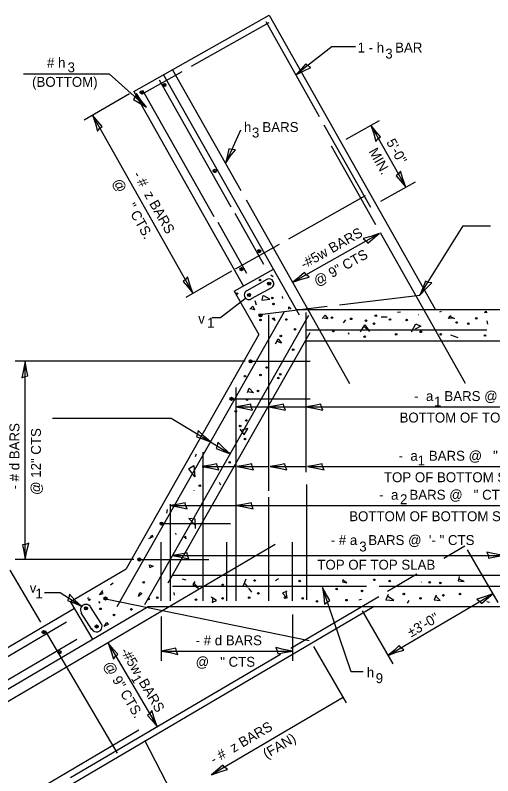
# Model space of a CAD drawing. Extents: x 2133490 to 2172050, y 2138301 to 2145980.
# Drawn here: x 2138402.7 to 2138691.7, y 2144827.1 to 2145287.5 of the extents above; entities that cross this region are included whole.
import ezdxf

# ---------------------------------------------------------------- set-up
doc = ezdxf.new("R2010")
doc.units = 0
for name, color, linetype in [('Level 40', 7, 'Continuous'), ('Level 63', 7, 'Continuous'), ('ROW_PR_Notes', 7, 'Continuous')]:
    doc.layers.add(name, color=color, linetype=linetype)

msp = doc.modelspace()

# ---------------------------------------------------------------- linework, layer by layer
at = {"layer": 'Level 40'}
msp.add_line((2138581.04, 2145095.24), (2138495.13, 2144943.62), dxfattribs=at)
for centre, radius in [((2138492.97, 2145245.3), 0.945), ((2138479.23, 2145240.84), 0.945), ((2138493.24, 2145245.3), 0.473), ((2138479.31, 2145240.65), 0.473), ((2138523.42, 2145193.34), 0.945), ((2138523.44, 2145193.28), 0.945), ((2138523.69, 2145192.86), 0.473), ((2138550.26, 2145144.7), 0.945), ((2138550.09, 2145144.79), 0.473), ((2138539.6, 2145133.83), 0.945), ((2138539.69, 2145133.64), 0.473), ((2138550.75, 2145127.23), 0.473), ((2138556.35, 2145125.03), 0.945), ((2138556.35, 2145125.03), 0.473), ((2138536.94, 2145119.02), 0.473), ((2138544.15, 2145118.22), 0.945), ((2138544.15, 2145118.22), 0.945), ((2138544.15, 2145118.22), 0.473), ((2138558.21, 2145116.41), 0.473), ((2138558.95, 2145112.68), 0.473), ((2138551.12, 2145105.86), 0.945), ((2138551.12, 2145105.86), 0.473), ((2138551.12, 2145102.98), 0.473), ((2138566.79, 2145103.35), 0.473), ((2138594.4, 2145104.47), 0.473), ((2138605.96, 2145103.73), 0.473), ((2138620.89, 2145105.59), 0.473), ((2138629.47, 2145103.35), 0.473), ((2138639.54, 2145102.98), 0.473), ((2138681.7, 2145104.1), 0.473), ((2138614.92, 2145102.61), 0.473), ((2138619.77, 2145100.74), 0.473), ((2138669.76, 2145101.49), 0.473), ((2138676.85, 2145100.74), 0.473), ((2138572.01, 2145097.38), 0.473), ((2138595.14, 2145096.26), 0.473), ((2138633.2, 2145094.4), 0.473), ((2138648.12, 2145095.89), 0.473), ((2138660.06, 2145094.4), 0.473), ((2138686.92, 2145093.65), 0.473), ((2138563.43, 2145093.28), 0.473), ((2138614.17, 2145092.91), 0.473), ((2138570.89, 2145085.07), 0.473), ((2138545.11, 2145078.02), 0.945), ((2138545.11, 2145078.02), 0.473), ((2138554.85, 2145074.25), 0.473), ((2138541.79, 2145069.03), 0.473), ((2138551.12, 2145069.77), 0.473), ((2138561.94, 2145067.91), 0.473), ((2138563.06, 2145070.15), 0.473), ((2138549.63, 2145060.07), 0.473), ((2138533.55, 2145055.34), 0.945), ((2138533.55, 2145055.34), 0.473), ((2138542.91, 2145054.85), 0.473), ((2138536.2, 2145047.76), 0.473), ((2138538.81, 2145038.81), 0.473), ((2138542.54, 2145042.17), 0.473), ((2138541.79, 2145030.97), 0.473), ((2138532.47, 2145016.8), 0.473), ((2138514.37, 2145002.8), 0.473), ((2138491.28, 2144979.74), 0.945), ((2138491.28, 2144979.74), 0.473), ((2138477.82, 2144958.01), 0.945), ((2138477.82, 2144958.01), 0.473), ((2138480.42, 2144944.23), 0.473), ((2138528.18, 2144942.74), 0.473), ((2138547.58, 2144945.35), 0.473), ((2138574.81, 2144944.97), 0.473), ((2138619.96, 2144945.72), 0.473), ((2138629.28, 2144944.97), 0.473), ((2138653.53, 2144944.23), 0.473), ((2138659.88, 2144943.86), 0.473), ((2138549.81, 2144937.51), 0.473), ((2138597.2, 2144940.13), 0.473), ((2138612.49, 2144939.01), 0.473), ((2138637.86, 2144937.14), 0.473), ((2138671.82, 2144937.14), 0.473), ((2138447.59, 2144933.78), 0.473), ((2138457.29, 2144934.44), 0.945), ((2138457.13, 2144934.29), 0.473), ((2138483.4, 2144934.16), 0.473), ((2138488.63, 2144934.9), 0.473), ((2138512.13, 2144933.78), 0.473), ((2138528.18, 2144934.53), 0.473), ((2138544.22, 2144934.9), 0.473), ((2138565.86, 2144934.9), 0.473), ((2138576.68, 2144934.53), 0.473), ((2138585.26, 2144932.66), 0.473), ((2138603.17, 2144933.41), 0.473), ((2138647.94, 2144934.53), 0.473), ((2138661.74, 2144936.39), 0.473), ((2138445.46, 2144928.53), 0.945), ((2138445.46, 2144928.53), 0.473), ((2138454.3, 2144928.19), 0.473), ((2138472.96, 2144927.81), 0.473), ((2138462.51, 2144924.46), 0.473), ((2138419.85, 2144914.03), 0.945), ((2138420.09, 2144914.03), 0.473), ((2138451.93, 2144917.48), 0.945), ((2138451.93, 2144917.48), 0.473), ((2138429.51, 2144901.95), 0.945), ((2138429.51, 2144901.46), 0.473)]:
    msp.add_circle(centre, radius, dxfattribs=at)
at = {"layer": 'Level 63'}
for p, q in [((2138594.52, 2145268.54), (2138608.64, 2145268.54)), ((2138471.92, 2145239.84), (2138444.31, 2145223.97)), ((2138449.38, 2145227.05), (2138510.11, 2145119.36)), ((2138603.03, 2145212.58), (2138623.1, 2145223.76)), ((2138617.83, 2145220.87), (2138638.96, 2145183.39)), ((2138623.95, 2145175.03), (2138644.99, 2145186.75)), ((2138647.61, 2145118.13), (2138673.81, 2145159.93)), ((2138673.81, 2145159.93), (2138690.2, 2145159.93)), ((2138570.76, 2145125.95), (2138623, 2145155.41)), ((2138533.57, 2145132.57), (2138505.95, 2145116.7)), ((2138541.81, 2145078.02), (2138402.72, 2145078.02)), ((2138408.72, 2144958.01), (2138408.72, 2145078.02)), ((2138536.31, 2145050.47), (2138556.16, 2145050.47)), ((2138556.16, 2145050.47), (2138578.77, 2145050.47)), ((2138578.77, 2145050.47), (2138787.43, 2145050.47)), ((2138515.84, 2145014.34), (2138536.18, 2145014.34)), ((2138536.93, 2145014.34), (2138556.22, 2145014.34)), ((2138556.97, 2145014.34), (2138578.5, 2145014.34)), ((2138579.53, 2145014.34), (2138767.82, 2145014.34)), ((2138496.67, 2144990.73), (2138535.86, 2144990.73)), ((2138536.7, 2144990.73), (2138749.98, 2144990.73)), ((2138497.8, 2144960.46), (2138697.99, 2144960.46)), ((2138676.17, 2144963.84), (2138694.65, 2144932.06)), ((2138474.51, 2144958.01), (2138402.72, 2144958.01)), ((2138418.12, 2144920.08), (2138399.59, 2144951.55)), ((2138628.24, 2144899.98), (2138691.65, 2144937.26)), ((2138570.45, 2144924.75), (2138570.45, 2144896.62)), ((2138612.58, 2144926.87), (2138631.23, 2144894.79)), ((2138491.07, 2144923.44), (2138491.07, 2144896.62)), ((2138458.88, 2144907.46), (2138488.61, 2144856.87)), ((2138491.07, 2144902.62), (2138570.45, 2144902.62)), ((2138481.01, 2144848.59), (2138497, 2144817.45))]:
    msp.add_line(p, q, dxfattribs=at)
for points in [[(2138581.66, 2145255.87), (2138579.83, 2145256.89), (2138578.45, 2145258.15), (2138575.9, 2145255.13), (2138572.49, 2145251.38), (2138577.29, 2145253.89)], [(2138475.99, 2145240.04), (2138475.31, 2145238.07), (2138474.31, 2145236.49), (2138477.73, 2145234.5), (2138482.03, 2145231.8), (2138478.71, 2145236.09)], [(2138452.47, 2145217.31), (2138453.75, 2145218.96), (2138455.2, 2145220.14), (2138452.6, 2145223.12), (2138449.38, 2145227.05), (2138451.16, 2145221.92)], [(2138620.92, 2145211.13), (2138622.19, 2145212.78), (2138623.64, 2145213.96), (2138621.04, 2145216.94), (2138617.83, 2145220.87), (2138619.6, 2145215.74)], [(2138535.91, 2145206.1), (2138533.82, 2145206.15), (2138532.01, 2145206.63), (2138531.15, 2145202.77), (2138529.87, 2145197.86), (2138532.96, 2145202.32)], [(2138635.87, 2145193.13), (2138634.6, 2145191.48), (2138633.14, 2145190.3), (2138635.75, 2145187.32), (2138638.96, 2145183.39), (2138637.18, 2145188.52)], [(2138613.26, 2145152.32), (2138614.91, 2145151.04), (2138616.09, 2145149.59), (2138619.07, 2145152.2), (2138623, 2145155.41), (2138617.88, 2145153.63)], [(2138580.5, 2145129.04), (2138578.85, 2145130.31), (2138577.67, 2145131.77), (2138574.69, 2145129.16), (2138570.76, 2145125.95), (2138575.89, 2145127.73)], [(2138507.02, 2145129.1), (2138505.74, 2145127.45), (2138504.29, 2145126.27), (2138506.9, 2145123.29), (2138510.11, 2145119.36), (2138508.33, 2145124.48)], [(2138654.69, 2145125.49), (2138652.63, 2145125.82), (2138650.9, 2145126.54), (2138649.53, 2145122.83), (2138647.61, 2145118.13), (2138651.26, 2145122.14)], [(2138406.63, 2145068.02), (2138408.55, 2145068.84), (2138410.4, 2145069.15), (2138409.59, 2145073.02), (2138408.72, 2145078.02), (2138407.75, 2145072.69)], [(2138546.31, 2145048.37), (2138545.5, 2145050.3), (2138545.18, 2145052.14), (2138541.31, 2145051.33), (2138536.31, 2145050.47), (2138541.65, 2145049.5)], [(2138566.15, 2145048.37), (2138565.34, 2145050.3), (2138565.03, 2145052.14), (2138561.16, 2145051.33), (2138556.16, 2145050.47), (2138561.49, 2145049.5)], [(2138588.77, 2145048.37), (2138587.96, 2145050.3), (2138587.64, 2145052.14), (2138583.77, 2145051.33), (2138578.77, 2145050.47), (2138584.11, 2145049.5)], [(2138513.35, 2145036.18), (2138513.05, 2145034.11), (2138512.36, 2145032.37), (2138516.09, 2145031.06), (2138520.82, 2145029.2), (2138516.76, 2145032.8)], [(2138525.22, 2145028.99), (2138524.92, 2145026.92), (2138524.23, 2145025.18), (2138527.96, 2145023.87), (2138532.68, 2145022.02), (2138528.62, 2145025.61)], [(2138525.84, 2145012.25), (2138525.02, 2145014.17), (2138524.71, 2145016.01), (2138520.84, 2145015.2), (2138515.84, 2145014.34), (2138521.17, 2145013.37)], [(2138546.93, 2145012.25), (2138546.11, 2145014.17), (2138545.8, 2145016.01), (2138541.93, 2145015.2), (2138536.93, 2145014.34), (2138542.26, 2145013.37)], [(2138566.97, 2145012.25), (2138566.15, 2145014.17), (2138565.84, 2145016.01), (2138561.97, 2145015.2), (2138556.97, 2145014.34), (2138562.3, 2145013.37)], [(2138589.53, 2145012.25), (2138588.71, 2145014.17), (2138588.4, 2145016.01), (2138584.53, 2145015.2), (2138579.53, 2145014.34), (2138584.86, 2145013.37)], [(2138506.66, 2144988.64), (2138505.85, 2144990.56), (2138505.54, 2144992.4), (2138501.67, 2144991.59), (2138496.67, 2144990.73), (2138502, 2144989.76)], [(2138546.7, 2144988.64), (2138545.88, 2144990.56), (2138545.57, 2144992.4), (2138541.7, 2144991.59), (2138536.7, 2144990.73), (2138542.03, 2144989.76)], [(2138410.82, 2144968), (2138408.89, 2144967.19), (2138407.05, 2144966.88), (2138407.86, 2144963.01), (2138408.72, 2144958.01), (2138409.69, 2144963.34)], [(2138507.8, 2144958.37), (2138506.99, 2144960.29), (2138506.67, 2144962.13), (2138502.8, 2144961.33), (2138497.8, 2144960.46), (2138503.14, 2144959.49)], [(2138687.99, 2144962.55), (2138688.8, 2144960.63), (2138689.12, 2144958.79), (2138692.99, 2144959.59), (2138697.99, 2144960.46), (2138692.65, 2144961.43)], [(2138589.89, 2144930.91), (2138591.45, 2144932.3), (2138593.09, 2144933.19), (2138591.08, 2144936.6), (2138588.65, 2144941.05), (2138589.45, 2144935.69)], [(2138435.5, 2144936.98), (2138435.14, 2144934.92), (2138434.4, 2144933.21), (2138438.09, 2144931.78), (2138442.76, 2144929.8), (2138438.8, 2144933.51)], [(2138681.97, 2144934), (2138683.65, 2144932.75), (2138684.85, 2144931.32), (2138687.78, 2144933.98), (2138691.65, 2144937.26), (2138686.56, 2144935.39)], [(2138462.14, 2144897.78), (2138463.38, 2144899.46), (2138464.81, 2144900.66), (2138462.16, 2144903.59), (2138458.88, 2144907.46), (2138460.74, 2144902.37)], [(2138637.92, 2144903.25), (2138636.24, 2144904.49), (2138635.04, 2144905.92), (2138632.11, 2144903.26), (2138628.24, 2144899.98), (2138633.33, 2144901.85)], [(2138501.07, 2144900.53), (2138500.25, 2144902.45), (2138499.94, 2144904.3), (2138496.07, 2144903.49), (2138491.07, 2144902.62), (2138496.4, 2144901.65)], [(2138560.45, 2144904.72), (2138561.27, 2144902.79), (2138561.58, 2144900.95), (2138565.45, 2144901.76), (2138570.45, 2144902.62), (2138565.12, 2144903.59)], [(2138485.35, 2144866.55), (2138484.1, 2144864.88), (2138482.67, 2144863.67), (2138485.33, 2144860.74), (2138488.61, 2144856.87), (2138486.74, 2144861.96)], [(2138531.16, 2144830.89), (2138529.49, 2144832.13), (2138528.28, 2144833.56), (2138525.35, 2144830.91), (2138521.48, 2144827.63), (2138526.57, 2144829.49)]]:
    msp.add_lwpolyline(points, close=True, dxfattribs=at)
at = {"layer": 'ROW_PR_Notes'}
for p, q in [((2138474.38, 2145241.25), (2138556.44, 2145287.53)), ((2138556.44, 2145287.53), (2138656.73, 2145109.67)), ((2138509.34, 2145256.63), (2138556.41, 2145283.17)), ((2138554.23, 2145283.74), (2138586.69, 2145226.18)), ((2138479.33, 2145239.71), (2138503.79, 2145253.5)), ((2138492.49, 2145251.46), (2138574.47, 2145106.09)), ((2138497.92, 2145254.52), (2138539.11, 2145181.47)), ((2138489.82, 2145248.44), (2138533.13, 2145171.62)), ((2138474.38, 2145241.25), (2138540.76, 2145123.54)), ((2138479.65, 2145242.18), (2138522.78, 2145165.68)), ((2138589.49, 2145221.22), (2138617.67, 2145171.25)), ((2138593.85, 2145208.52), (2138620.76, 2145160.8)), ((2138568.25, 2145152.15), (2138614.72, 2145178.35)), ((2138542.36, 2145175.71), (2138605.03, 2145064.58)), ((2138535.57, 2145167.63), (2138552.94, 2145136.82)), ((2138525.23, 2145162.24), (2138542.6, 2145131.43)), ((2138623.42, 2145156.09), (2138674.94, 2145064.72)), ((2138536.03, 2145133.98), (2138562.7, 2145149.02)), ((2138535.26, 2145120.44), (2138558.88, 2145133.76)), ((2138554.96, 2145127.51), (2138542.76, 2145120.69)), ((2138557.27, 2145130.4), (2138558.77, 2145129.28)), ((2138557.73, 2145122.56), (2138545.53, 2145115.75)), ((2138535.26, 2145120.44), (2138550.05, 2145094.22)), ((2138552.53, 2145117.92), (2138551.85, 2145114.99)), ((2138556.81, 2145115.67), (2138553.2, 2145117.7)), ((2138564.25, 2145117.25), (2138564.48, 2145116.12)), ((2138598.83, 2145112.21), (2138647.61, 2145118.13)), ((2138526.86, 2145104.5), (2138542.06, 2145116.23)), ((2138548.7, 2145112.06), (2138547.79, 2145114.54)), ((2138551.85, 2145114.99), (2138556.81, 2145115.67)), ((2138565.42, 2145107.92), (2138464.24, 2144929.36)), ((2138544.59, 2145109.51), (2138546.45, 2145111.37)), ((2138547.57, 2145109.13), (2138544.96, 2145109.88)), ((2138546.45, 2145111.37), (2138547.57, 2145109.13)), ((2138550.8, 2145106.38), (2138591.4, 2145111.31)), ((2138568.25, 2145109.54), (2138568.25, 2145111.08)), ((2138568.25, 2145111.08), (2138569.45, 2145110.05)), ((2138569.45, 2145110.05), (2138568.77, 2145109.71)), ((2138813.89, 2145109.21), (2138572.71, 2145109.21)), ((2138634.01, 2145107.83), (2138635.89, 2145108)), ((2138659.52, 2145108), (2138660.72, 2145108.34)), ((2138686.57, 2145107.65), (2138687.6, 2145108.34)), ((2138687.94, 2145107.31), (2138686.92, 2145108)), ((2138687.6, 2145108.34), (2138687.94, 2145107.31)), ((2138580.17, 2145105.81), (2138480.91, 2144930.66)), ((2138521.86, 2145104.5), (2138526.86, 2145104.5)), ((2138556.16, 2144999.6), (2138556.16, 2145106.21)), ((2138559.86, 2145102.69), (2138558.15, 2145103.89)), ((2138558.84, 2145103.72), (2138559.18, 2145104.57)), ((2138559.18, 2145104.57), (2138559.86, 2145102.69)), ((2138578.77, 2145011.01), (2138578.77, 2145107.59)), ((2138588.37, 2145103.95), (2138590.18, 2145105.98)), ((2138591.76, 2145103.72), (2138589.5, 2145104.17)), ((2138590.18, 2145105.98), (2138591.76, 2145103.72)), ((2138601.3, 2145101.3), (2138602.79, 2145103.17)), ((2138624.06, 2145105.03), (2138627.79, 2145105.03)), ((2138646.63, 2145106.34), (2138647, 2145106.34)), ((2138666.15, 2145105.75), (2138664.8, 2145103.95)), ((2138664.8, 2145103.95), (2138665.7, 2145105.3)), ((2138668.41, 2145103.95), (2138665.48, 2145104.17)), ((2138665.7, 2145105.3), (2138668.41, 2145103.95)), ((2138611.59, 2145095.83), (2138614.3, 2145100.11)), ((2138617, 2145096.06), (2138613.4, 2145099.44)), ((2138614.3, 2145100.11), (2138617, 2145096.06)), ((2138636.93, 2145101.49), (2138636.93, 2145101.49)), ((2138643.65, 2145098.13), (2138645.14, 2145100.74)), ((2138648.12, 2145099.25), (2138644.76, 2145097.38)), ((2138645.14, 2145100.74), (2138648.12, 2145099.25)), ((2138688.7, 2145100.57), (2138688.25, 2145102.59)), ((2138550.05, 2145094.22), (2138469.73, 2144952.47)), ((2138688.06, 2145096.84), (2138578.25, 2145096.84)), ((2138604.1, 2145095.52), (2138604.47, 2145094.4)), ((2138623.13, 2145094.77), (2138623.13, 2145094.77)), ((2138642.53, 2145095.89), (2138643.65, 2145098.13)), ((2138666.03, 2145094.02), (2138670.51, 2145092.53)), ((2138560.19, 2145088.62), (2138561.77, 2145091.55)), ((2138563.8, 2145089.07), (2138561.09, 2145089.97)), ((2138561.77, 2145091.55), (2138563.8, 2145089.07)), ((2138822.46, 2145090.31), (2138578.25, 2145090.31)), ((2138545.11, 2145078.02), (2138581.21, 2145078.02)), ((2138536.31, 2144933.03), (2138536.31, 2145062.17)), ((2138543.28, 2145059.08), (2138544.19, 2145061.79)), ((2138544.19, 2145061.79), (2138546.89, 2145058.86)), ((2138546.89, 2145058.86), (2138543.28, 2145059.53)), ((2138533.55, 2145055.34), (2138581.21, 2145055.34)), ((2138425.15, 2145043.63), (2138497, 2145043.63)), ((2138497, 2145043.63), (2138520.82, 2145029.2)), ((2138538.55, 2145036.99), (2138541.25, 2145033.61)), ((2138543.51, 2145037.44), (2138539.9, 2145036.31)), ((2138541.25, 2145033.61), (2138543.51, 2145037.44)), ((2138520.82, 2145029.21), (2138532.68, 2145022.02)), ((2138511.72, 2145020.31), (2138512.4, 2145022.11)), ((2138516.47, 2144933.03), (2138516.47, 2145023.05)), ((2138507.44, 2145012.87), (2138510.82, 2145014.9)), ((2138511.27, 2145008.13), (2138507.66, 2145012.87)), ((2138510.82, 2145014.9), (2138511.27, 2145008.13)), ((2138527.05, 2145002.95), (2138526.37, 2145004.75)), ((2138579.23, 2144933.72), (2138579.23, 2145003.41)), ((2138510.82, 2144999.79), (2138510.82, 2144999.56)), ((2138556.16, 2144933.03), (2138556.16, 2144995.8)), ((2138494.59, 2144988.29), (2138494.14, 2144986.04)), ((2138496.62, 2144933.03), (2138496.62, 2144991.51)), ((2138491.28, 2144979.74), (2138532.96, 2144979.74)), ((2138511.5, 2144982.43), (2138507.66, 2144982.88)), ((2138507.66, 2144982.88), (2138511.95, 2144978.37)), ((2138511.72, 2144976.79), (2138511.5, 2144982.43)), ((2138485.92, 2144971.75), (2138483.31, 2144970.62)), ((2138484.43, 2144971), (2138485.27, 2144972.68)), ((2138485.27, 2144972.68), (2138485.92, 2144971.75)), ((2138499.72, 2144973.89), (2138499.91, 2144973.14)), ((2138504.39, 2144972.21), (2138506.07, 2144970.53)), ((2138505.97, 2144971.93), (2138504.67, 2144971.28)), ((2138506.07, 2144970.53), (2138505.97, 2144971.93)), ((2138358.9, 2144849.08), (2138559.98, 2144967.27)), ((2138491.07, 2144933.03), (2138491.07, 2144968.59)), ((2138530.76, 2144933.03), (2138530.76, 2144968.59)), ((2138570.45, 2144933.03), (2138570.45, 2144968.59)), ((2138662, 2144958.8), (2138674.75, 2144966.29)), ((2138477.82, 2144958.01), (2138519.8, 2144958.01)), ((2138436.1, 2144932.7), (2138469.73, 2144952.47)), ((2138486.11, 2144953.93), (2138483.87, 2144953.09)), ((2138484.15, 2144953.28), (2138483.96, 2144954.86)), ((2138483.96, 2144954.86), (2138486.11, 2144953.93)), ((2138497.92, 2144948.56), (2138746.73, 2144948.56)), ((2138627.96, 2144938.79), (2138645.78, 2144949.27)), ((2138671.34, 2144947.71), (2138670.66, 2144945.23)), ((2138460.27, 2144942.64), (2138461.85, 2144943.86)), ((2138503.61, 2144946.36), (2138505.86, 2144945.68)), ((2138511.27, 2144944.78), (2138510.14, 2144942.98)), ((2138510.14, 2144942.98), (2138513.52, 2144940.72)), ((2138513.52, 2144940.72), (2138510.59, 2144944.11)), ((2138542.16, 2144946.13), (2138540.58, 2144942.08)), ((2138540.58, 2144942.08), (2138543.73, 2144941.4)), ((2138543.73, 2144941.4), (2138541.71, 2144943.43)), ((2138562, 2144946.36), (2138560.19, 2144945.23)), ((2138601.22, 2144945.91), (2138600.77, 2144944.56)), ((2138600.77, 2144944.56), (2138603.25, 2144943.88)), ((2138603.25, 2144943.88), (2138601, 2144945.46)), ((2138648.34, 2144944.33), (2138648.57, 2144944.56)), ((2138670.66, 2144945.23), (2138674.27, 2144944.78)), ((2138674.27, 2144944.78), (2138670.89, 2144946.36)), ((2138455.42, 2144939.29), (2138453.65, 2144936.77)), ((2138453.65, 2144936.77), (2138455.89, 2144937.42)), ((2138455.89, 2144937.42), (2138455.23, 2144938.73)), ((2138477.34, 2144935.93), (2138477.99, 2144937.98)), ((2138479.3, 2144937.42), (2138477.34, 2144935.74)), ((2138477.99, 2144937.98), (2138479.3, 2144937.42)), ((2138497.92, 2144941.94), (2138615.2, 2144941.94)), ((2138499.1, 2144936.44), (2138498.87, 2144938.02)), ((2138545.76, 2144938.24), (2138543.96, 2144940.72)), ((2138566.95, 2144938.92), (2138564.48, 2144937.57)), ((2138564.48, 2144937.57), (2138567.18, 2144934.64)), ((2138567.18, 2144934.64), (2138566.73, 2144938.69)), ((2138622.97, 2144941.94), (2138854.21, 2144941.94)), ((2138446.37, 2144934.34), (2138447.12, 2144935)), ((2138457.24, 2144934.29), (2138580.61, 2144909.06)), ((2138524.57, 2144933.28), (2138521.19, 2144935.31)), ((2138522.32, 2144935.09), (2138521.87, 2144931.93)), ((2138521.87, 2144931.93), (2138524.57, 2144933.28)), ((2138569.4, 2144904.37), (2138622.69, 2144935.69)), ((2138610.69, 2144933.73), (2138612.27, 2144933.96)), ((2138628.28, 2144936.89), (2138626.92, 2144933.73)), ((2138626.92, 2144933.73), (2138631.88, 2144933.28)), ((2138631.88, 2144933.28), (2138628.05, 2144935.76)), ((2138640, 2144931.71), (2138641.13, 2144933.28)), ((2138657.36, 2144936.44), (2138656.23, 2144933.73)), ((2138656.23, 2144933.73), (2138659.84, 2144933.28)), ((2138659.84, 2144933.28), (2138656.91, 2144935.99)), ((2138267.41, 2144828.06), (2138438.49, 2144928.63)), ((2138278.6, 2144809.43), (2138483.14, 2144929.66)), ((2138313.5, 2144749.65), (2138619.82, 2144929.7)), ((2138449.75, 2144909.48), (2138436.1, 2144932.7)), ((2138454.72, 2144919.26), (2138448.25, 2144929.37)), ((2138454.11, 2144931.64), (2138453.27, 2144932.66)), ((2138483.14, 2144929.66), (2138723.07, 2144929.66)), ((2138688.02, 2144932.61), (2138689.6, 2144932.16)), ((2138449.14, 2144915.69), (2138442.67, 2144925.8)), ((2138363.17, 2144878.87), (2138433.71, 2144920.33)), ((2138456.44, 2144917.46), (2138458.03, 2144919.98)), ((2138458.03, 2144919.98), (2138458.87, 2144918.67)), ((2138464.67, 2144840.71), (2138421.03, 2144914.95)), ((2138458.87, 2144918.67), (2138456.73, 2144917.74)), ((2138369.4, 2144868.28), (2138439.94, 2144909.75)), ((2138583.26, 2144905.32), (2138603, 2144871.37)), ((2138436.05, 2144825.99), (2138563.12, 2144900.68)), ((2138601.09, 2144874.42), (2138521.48, 2144827.63)), ((2138312.9, 2144758.13), (2138477.47, 2144854.86))]:
    msp.add_line(p, q, dxfattribs=at)
for points in [[(2138594.52, 2145268.54), (2138572.49, 2145251.38)], [(2138407.7, 2145252.08), (2138459.47, 2145252.08), (2138482.03, 2145231.8)], [(2138539.02, 2145218.01), (2138529.87, 2145197.86)], [(2138420.38, 2144938.15), (2138429.83, 2144938.15), (2138442.76, 2144929.8)], [(2138613.29, 2144890.03), (2138606.03, 2144890.03), (2138588.65, 2144941.05)]]:
    msp.add_lwpolyline(points, dxfattribs=at)
for centre, radius, start, end in [((2138556.35, 2145125.03), 2.83, 299.1882, 119.1882), ((2138544.15, 2145118.22), 2.83, 119.1882, 299.1882), ((2138445.46, 2144927.58), 3.31, 24.2368, 215.3019), ((2138451.93, 2144917.48), 3.31, 198.1943, 38.5711)]:
    msp.add_arc(centre, radius, start, end, dxfattribs=at)

# ---------------------------------------------------------------- texts
at = {"layer": 'Level 63'}
for s, height, rotation, p in [('5\'-0"', 6, 299.4181, (2138627, 2145210.7)), ('MIN.', 6, 299.4181, (2138616.39, 2145205.1)), ('   - #  z BARS', 6, 299.4186, (2138470.43, 2145196.84)), ('@    " CTS.', 6, 299.4186, (2138461.28, 2145186.61)), (' -#5w BARS', 6, 29.4185, (2138575.47, 2145132.62)), ('@ 9" CTS', 6, 29.4185, (2138585.37, 2145123.28)), ('   - # d BARS', 6, 90, (2138405.22, 2144993.78)), ('@ 12" CTS', 6, 90, (2138418.22, 2144997.12)), ('±3\'-0"', 6, 30.4463, (2138642.16, 2144910.75)), (' -#5w  BARS', 6, 300.4461, (2138464.98, 2144904.49)), ('@ 9" CTS.', 6, 300.4461, (2138455.89, 2144894.29)), ('1', 5.67, 300.4459, (2138472.58, 2144886.05))]:
    msp.add_text(s, height=height, rotation=rotation, dxfattribs=at).set_placement(p)
for s, p in [('   -  a   BARS @   " CTS', (2138637.41, 2145053.97)), ('1', (2138656.12, 2145050.68)), ('BOTTOM OF TOP SLAB', (2138635.23, 2145040.97)), ('   -  a   BARS @   " CTS', (2138627.99, 2145017.84)), ('1', (2138646.14, 2145014.98)), ('TOP OF BOTTOM SLAB', (2138625.81, 2145004.84)), ('   -  a   BARS @   " CTS', (2138616.26, 2144994.23)), ('2', (2138635.53, 2144991.54)), ('BOTTOM OF BOTTOM SLAB', (2138604.77, 2144981.23)), ('   - # a   BARS @  \'- " CTS', (2138586.9, 2144966.81)), ('3', (2138610.87, 2144962.9)), ('TOP OF TOP SLAB', (2138585.52, 2144951.89)), ('  - # d BARS', (2138507.39, 2144906.12)), ('@   " CTS', (2138511.89, 2144893.12))]:
    msp.add_text(s, height=6, dxfattribs=at).set_placement(p)
at = {"layer": 'ROW_PR_Notes'}
for s, p in [('1 - h   BAR', (2138609.84, 2145264.95)), ('3', (2138626.64, 2145261.3)), ('  # h ', (2138417.45, 2145255.85)), ('3', (2138434.37, 2145252.96)), ('(BOTTOM)', (2138412.87, 2145244.17)), ('h   BARS', (2138541.11, 2145216.82)), ('3', (2138545.93, 2145213.5)), ('v', (2138513.41, 2145100.87)), ('1', (2138518.82, 2145098.41)), ('v', (2138411.46, 2144937.89)), ('1', (2138414.92, 2144934.45)), ('h', (2138615.43, 2144886.71)), ('9', (2138620.82, 2144883.22))]:
    msp.add_text(s, height=6, dxfattribs=at).set_placement(p)
for s, p in [('  - #  z BARS', (2138519.04, 2144831.68)), ('(FAN)', (2138554.75, 2144837.31))]:
    msp.add_text(s, height=6, rotation=30.4467, dxfattribs=at).set_placement(p)

doc.saveas('drawing.dxf')
